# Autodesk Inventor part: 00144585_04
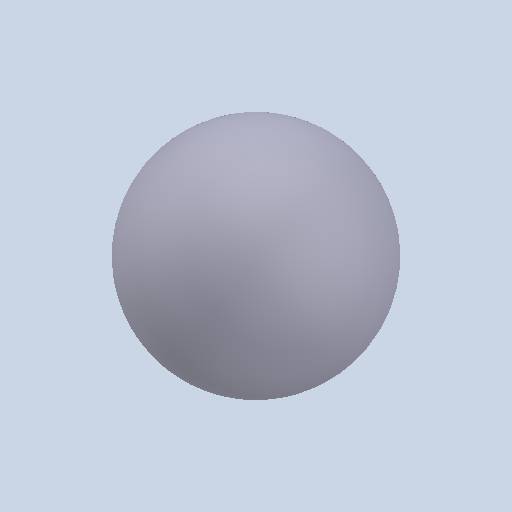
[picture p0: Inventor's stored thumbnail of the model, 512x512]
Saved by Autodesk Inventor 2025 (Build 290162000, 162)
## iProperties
Created: 2021-02
Part Number: 00144585_04
Material: Generico
Document SubType Name: Modeling
Designer: Ryzen5700u
Density: 1 g/cm^3
Appearance: Default
Author: Ryzen5700u
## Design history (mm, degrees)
feature "Solido1"
node "Solido2"
